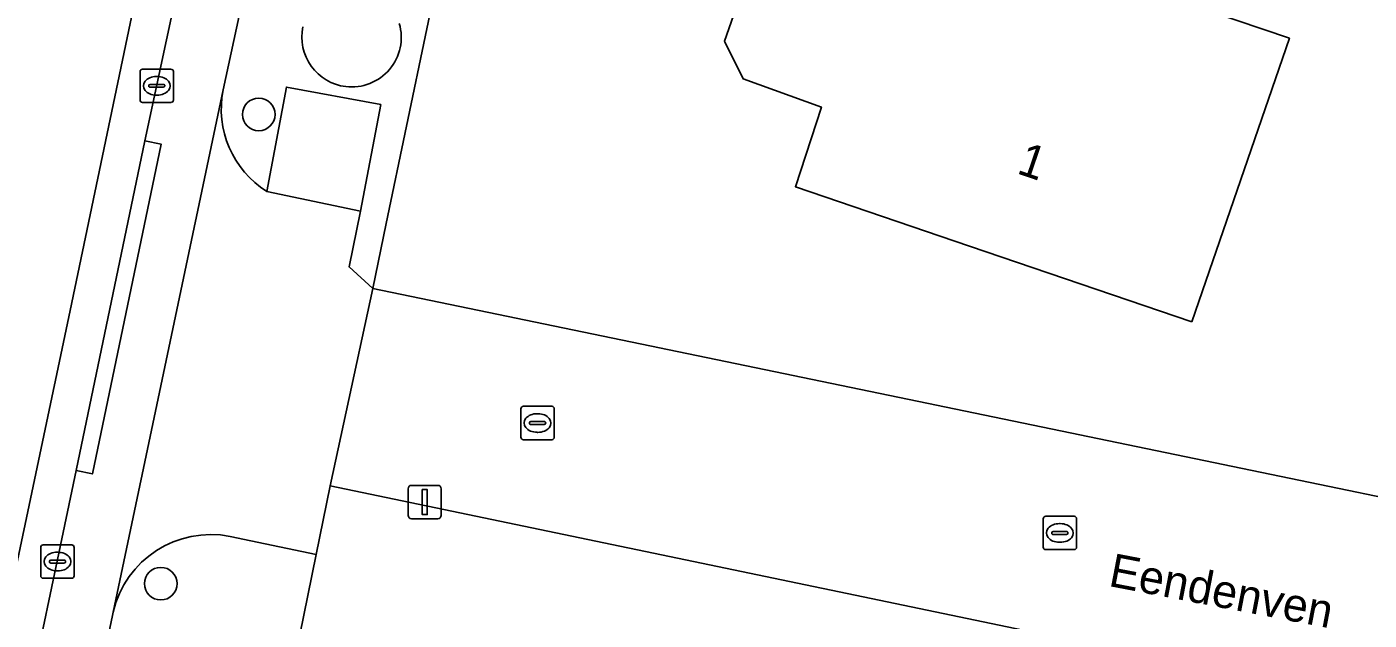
# Model space of a CAD drawing. Extents: x 163426 to 164192, y 380329 to 381641.
# Drawn here: x 163885.21 to 163925.42, y 380973.51 to 380991.3 of the extents above; entities that cross this region are included whole.
import ezdxf

# ---------------------------------------------------------------- set-up
doc = ezdxf.new("R2010")
doc.units = 0
for name, color, linetype in [('IMGEO_Boom', 7, 'Continuous'), ('IMGEO_Erf', 7, 'Continuous'), ('IMGEO_Groenvoorziening', 7, 'Continuous'), ('IMGEO_Kolk', 7, 'Continuous'), ('IMGEO_Lichtmast', 7, 'Continuous'), ('IMGEO_Openbare_ruimte_label', 7, 'Continuous'), ('IMGEO_Pand', 7, 'Continuous'), ('IMGEO_Pand_nummerreeks', 7, 'Continuous'), ('IMGEO_Rijbaan_lokaal_open', 7, 'Continuous'), ('IMGEO_Voetpad_open', 7, 'Continuous'), ('IMGEO_Waterloop', 7, 'Continuous')]:
    doc.layers.add(name, color=color, linetype=linetype)

msp = doc.modelspace()

# ---------------------------------------------------------------- linework, layer by layer
at = {"layer": 'IMGEO_Boom'}
for centre in [(163892.154, 380988.669), (163889.22, 380974.6)]:
    msp.add_circle(centre, 0.489, dxfattribs=at)
at = {"layer": 'IMGEO_Erf'}
for points in [[(163947.717, 380966.396), (163894.299, 380977.535), (163893.879, 380975.478), (163890.647, 380959.592), (163890.731, 380956.366), (163893.555, 380954.822), (163905.172, 380951.086), (163923.758, 380944.858), (164044.028, 380904.553), (164047.573, 380932.485), (164051.149, 380955.68), (164051.075, 380964.76), (164050.906, 381000), (164050.855, 381010.828), (164044.976, 381010.935), (164033.301, 381009.851), (164028.463, 381008.901), (164025.441, 381000), (164017.396, 380976.301), (164021.658, 380974.921), (164011.506, 380944.546), (164004.376, 380947.063), (164007.582, 380956.643)], [(164022.57, 381000), (164024.898, 381006.842), (164025.394, 381008.299), (164023.996, 381008.024), (164000, 381002.141), (163996.432, 381001.266), (163991.135, 381000), (163970.466, 380995.06), (163967.625, 380994.381), (163961.405, 380993.65), (163960.215, 380993.613), (163954.592, 380993.795), (163949.019, 380994.564), (163937.098, 380997.759), (163924.687, 381000), (163899.949, 381004.467), (163899.243, 381001.078), (163899.018, 381000), (163895.976, 380985.403), (163895.569, 380983.45), (163954.825, 380971.177)]]:
    msp.add_lwpolyline(points, dxfattribs=at)
msp.add_lwpolyline([(163920.112, 380982.451), (163913.447, 380984.724), (163908.231, 380986.502), (163909.013, 380988.891), (163906.664, 380989.735), (163906.111, 380990.867), (163906.799, 380992.842), (163907.896, 380993.375), (163910.328, 380992.556), (163911.147, 380994.987), (163923.033, 380990.953)], close=True, dxfattribs=at)
at = {"layer": 'IMGEO_Groenvoorziening'}
for points in [[(163899.018, 381000), (163899.243, 381001.078), (163897.624, 381001.36), (163893.814, 381002.022), (163893.377, 381000), (163891.085, 380989.403)], [(163892.395, 380986.356), (163892.983, 380989.49), (163895.81, 380988.967), (163895.2, 380985.771), (163894.863, 380984.096), (163895.569, 380983.45), (163895.976, 380985.403), (163899.018, 381000)], [(163887.797, 380973.745), (163887.786, 380973.694), (163887.776, 380973.643), (163885.067, 380960.77), (163883.083, 380951.119), (163905.684, 380943.493), (163921.538, 380938.092), (163921.833, 380938.946), (163922.56, 380941.188), (163923.758, 380944.858), (163905.172, 380951.086), (163893.555, 380954.822), (163890.731, 380956.366), (163890.647, 380959.592), (163893.879, 380975.478), (163891.917, 380975.887), (163891.302, 380976.015)]]:
    msp.add_lwpolyline(points, dxfattribs=at)
msp.add_lwpolyline([(163892.395, 380986.356), (163895.2, 380985.771), (163895.81, 380988.967), (163892.983, 380989.49)], close=True, dxfattribs=at)
for centre, radius, start, end in [((163894.937, 380990.984), 1.49, 167.9108, 263.2069), ((163894.936, 380990.982), 1.489, 263.245, 16.1386), ((163893.985, 380988.845), 2.953, 169.1045, 237.4243), ((163890.716, 380973.078), 2.995, 78.7234, 167.1345)]:
    msp.add_arc(centre, radius, start, end, dxfattribs=at)
at = {"layer": 'IMGEO_Kolk'}
for p, q in [((163888.599, 380989.101), (163888.599, 380989.953)), ((163888.674, 380990.027), (163889.526, 380990.027)), ((163889.087, 380989.807), (163889.112, 380989.807)), ((163889.6, 380989.953), (163889.6, 380989.101)), ((163888.858, 380989.521), (163888.858, 380989.533)), ((163889.296, 380989.484), (163888.898, 380989.484)), ((163888.901, 380989.57), (163889.299, 380989.57)), ((163889.342, 380989.533), (163889.342, 380989.521)), ((163889.526, 380989.027), (163888.674, 380989.027)), ((163889.11, 380989.247), (163889.085, 380989.247)), ((163900.008, 380978.991), (163900.008, 380979.843)), ((163900.083, 380979.917), (163900.935, 380979.917)), ((163901.009, 380979.843), (163901.009, 380978.991)), ((163900.267, 380979.411), (163900.267, 380979.423)), ((163900.705, 380979.374), (163900.307, 380979.374)), ((163900.31, 380979.46), (163900.708, 380979.46)), ((163900.496, 380979.697), (163900.521, 380979.697)), ((163900.751, 380979.423), (163900.751, 380979.411)), ((163900.519, 380979.137), (163900.494, 380979.137)), ((163900.935, 380978.917), (163900.083, 380978.917)), ((163915.656, 380975.694), (163915.656, 380976.546)), ((163915.731, 380976.62), (163916.583, 380976.62)), ((163916.657, 380976.546), (163916.657, 380975.694)), ((163915.915, 380976.114), (163915.915, 380976.126)), ((163915.958, 380976.163), (163916.356, 380976.163)), ((163916.144, 380976.4), (163916.169, 380976.4)), ((163916.399, 380976.126), (163916.399, 380976.114)), ((163885.699, 380975.762), (163886.551, 380975.762)), ((163916.353, 380976.077), (163915.955, 380976.077)), ((163916.167, 380975.84), (163916.142, 380975.84)), ((163885.624, 380974.836), (163885.624, 380975.688)), ((163886.112, 380975.542), (163886.137, 380975.542)), ((163886.625, 380975.688), (163886.625, 380974.836)), ((163916.583, 380975.62), (163915.731, 380975.62)), ((163885.883, 380975.256), (163885.883, 380975.268)), ((163886.321, 380975.219), (163885.923, 380975.219)), ((163885.926, 380975.305), (163886.324, 380975.305)), ((163886.135, 380974.982), (163886.11, 380974.982)), ((163886.367, 380975.268), (163886.367, 380975.256)), ((163886.551, 380974.762), (163885.699, 380974.762))]:
    msp.add_line(p, q, dxfattribs=at)
for points in [[(163888.599, 380989.101), (163888.599, 380989.953)], [(163888.674, 380990.027), (163889.526, 380990.027)], [(163889.6, 380989.953), (163889.6, 380989.101)], [(163889.526, 380989.027), (163888.674, 380989.027)], [(163900.008, 380978.991), (163900.008, 380979.843)], [(163900.083, 380979.917), (163900.935, 380979.917)], [(163901.009, 380979.843), (163901.009, 380978.991)], [(163900.935, 380978.917), (163900.083, 380978.917)], [(163915.656, 380975.694), (163915.656, 380976.546)], [(163915.731, 380976.62), (163916.583, 380976.62)], [(163916.657, 380976.546), (163916.657, 380975.694)], [(163885.699, 380975.762), (163886.551, 380975.762)], [(163885.624, 380974.836), (163885.624, 380975.688)], [(163886.625, 380975.688), (163886.625, 380974.836)], [(163916.583, 380975.62), (163915.731, 380975.62)], [(163886.551, 380974.762), (163885.699, 380974.762)]]:
    msp.add_lwpolyline(points, dxfattribs=at)
for centre, radius, start, end in [((163888.676, 380989.951), 0.0765, 91.552, 178.448), ((163888.676, 380989.951), 0.0765, 91.552, 178.448), ((163889.524, 380989.951), 0.0765, 1.552, 88.448), ((163889.524, 380989.951), 0.0765, 1.552, 88.448), ((163888.898, 380989.53), 0.0403, 85.8775, 175.7526), ((163888.895, 380989.52), 0.0366, 178.938, 274.7102), ((163889.299, 380989.527), 0.043, 264.8664, 352.4533), ((163889.303, 380989.532), 0.0386, 1.7309, 96.639), ((163888.676, 380989.103), 0.0765, 181.552, 268.448), ((163888.676, 380989.103), 0.0765, 181.552, 268.448), ((163889.524, 380989.103), 0.0765, 271.552, 358.448), ((163889.524, 380989.103), 0.0765, 271.552, 358.448), ((163900.085, 380979.841), 0.0765, 91.552, 178.448), ((163900.085, 380979.841), 0.0765, 91.552, 178.448), ((163900.933, 380979.841), 0.0765, 1.552, 88.448), ((163900.933, 380979.841), 0.0765, 1.552, 88.448), ((163900.307, 380979.42), 0.0403, 85.8775, 175.7526), ((163900.304, 380979.41), 0.0366, 178.938, 274.7102), ((163900.708, 380979.417), 0.043, 264.8664, 352.4533), ((163900.712, 380979.422), 0.0386, 1.7309, 96.639), ((163900.085, 380978.993), 0.0765, 181.552, 268.448), ((163900.085, 380978.993), 0.0765, 181.552, 268.448), ((163900.933, 380978.993), 0.0765, 271.552, 358.448), ((163900.933, 380978.993), 0.0765, 271.552, 358.448), ((163915.733, 380976.544), 0.0765, 91.552, 178.448), ((163915.733, 380976.544), 0.0765, 91.552, 178.448), ((163916.581, 380976.544), 0.0765, 1.552, 88.448), ((163916.581, 380976.544), 0.0765, 1.552, 88.448), ((163915.955, 380976.123), 0.0403, 85.8775, 175.7526), ((163916.36, 380976.125), 0.0386, 1.7309, 96.639), ((163885.701, 380975.686), 0.0765, 91.552, 178.448), ((163885.701, 380975.686), 0.0765, 91.552, 178.448), ((163886.549, 380975.686), 0.0765, 1.552, 88.448), ((163886.549, 380975.686), 0.0765, 1.552, 88.448), ((163915.952, 380976.113), 0.0366, 178.938, 274.7102), ((163916.356, 380976.12), 0.043, 264.8664, 352.4533), ((163915.733, 380975.696), 0.0765, 181.552, 268.448), ((163915.733, 380975.696), 0.0765, 181.552, 268.448), ((163916.581, 380975.696), 0.0765, 271.552, 358.448), ((163916.581, 380975.696), 0.0765, 271.552, 358.448), ((163885.923, 380975.265), 0.0403, 85.8775, 175.7526), ((163885.92, 380975.255), 0.0366, 178.938, 274.7102), ((163886.324, 380975.262), 0.043, 264.8664, 352.4533), ((163886.328, 380975.267), 0.0386, 1.7309, 96.639), ((163885.701, 380974.838), 0.0765, 181.552, 268.448), ((163885.701, 380974.838), 0.0765, 181.552, 268.448), ((163886.549, 380974.838), 0.0765, 271.552, 358.448), ((163886.549, 380974.838), 0.0765, 271.552, 358.448)]:
    msp.add_arc(centre, radius, start, end, dxfattribs=at)
for centre, major_axis, ratio, start_param, end_param in [((163889.086, 380989.527), (-0.387, 0.002), 0.722429, 4.712389, 7.853982), ((163889.111, 380989.527), (-0.39, 0.002), 0.717154, 1.570796, 4.712389), ((163900.495, 380979.417), (-0.387, 0.002), 0.722429, 4.712389, 7.853982), ((163900.52, 380979.417), (-0.39, 0.002), 0.717154, 1.570796, 4.712389), ((163916.143, 380976.12), (-0.387, 0.002), 0.722429, 4.712389, 7.853982), ((163916.168, 380976.12), (-0.39, 0.002), 0.717154, 1.570796, 4.712389), ((163886.111, 380975.262), (-0.387, 0.002), 0.722429, 4.712389, 7.853982), ((163886.136, 380975.262), (-0.39, 0.002), 0.717154, 1.570796, 4.712389)]:
    msp.add_ellipse(centre, major_axis=major_axis, ratio=ratio, start_param=start_param, end_param=end_param, dxfattribs=at)
at = {"layer": 'IMGEO_Lichtmast'}
for p, q in [((163896.632, 380976.648), (163896.632, 380977.448)), ((163896.632, 380977.448), (163896.632, 380976.648)), ((163896.732, 380977.548), (163897.522, 380977.548)), ((163897.522, 380977.548), (163896.732, 380977.548)), ((163897.622, 380977.448), (163897.622, 380976.648)), ((163897.622, 380976.648), (163897.622, 380977.448)), ((163897.522, 380976.548), (163896.732, 380976.548)), ((163896.732, 380976.548), (163897.522, 380976.548))]:
    msp.add_line(p, q, dxfattribs=at)
msp.add_lwpolyline([(163897.052, 380977.423), (163897.202, 380977.423), (163897.202, 380976.673), (163897.052, 380976.673), (163897.052, 380977.423)], dxfattribs=at)
for centre, start, end in [((163896.732, 380977.448), 90, 180), ((163896.732, 380977.448), 90, 180), ((163897.522, 380977.448), 0, 90), ((163897.522, 380977.448), 360, 90), ((163896.732, 380976.648), 180, 270), ((163896.732, 380976.648), 180, 270), ((163897.522, 380976.648), 270, 0), ((163897.522, 380976.648), 270, 0)]:
    msp.add_arc(centre, 0.1, start, end, dxfattribs=at)
at = {"layer": 'IMGEO_Pand'}
msp.add_lwpolyline([(163920.112, 380982.451), (163923.033, 380990.953), (163911.147, 380994.987), (163910.328, 380992.556), (163907.896, 380993.375), (163906.799, 380992.842), (163906.111, 380990.867), (163906.664, 380989.735), (163909.013, 380988.891), (163908.231, 380986.502), (163913.447, 380984.724)], close=True, dxfattribs=at)
at = {"layer": 'IMGEO_Rijbaan_lokaal_open'}
for points in [[(163921.638, 381053.716), (163922.311, 381054.818), (163921.501, 381055.887), (163917.721, 381049.86), (163902.377, 381023.75), (163895.208, 381011.818), (163892.059, 381006.187), (163890.987, 381003.841), (163890.009, 380999.579), (163886.502, 380982.789), (163875.39, 380930.027), (163874.806, 380927.256), (163873.655, 380925.227), (163872.124, 380924.818), (163868.839, 380925.415), (163868.546, 380923.98), (163875.141, 380922.738), (163879.435, 380943.25), (163880.93, 380950.483), (163883.139, 380961.124), (163886.682, 380977.995), (163888.743, 380987.877), (163891.335, 381000), (163891.536, 381000.938)], [(163909.614, 381043.056), (163891.389, 381012.622), (163887.972, 381006.053), (163887.168, 381003.975), (163886.431, 381000.422), (163877.536, 380958.937), (163873.3, 380937.44), (163872.302, 380935.525), (163871.122, 380934.091), (163870.508, 380933.6), (163868.839, 380925.415), (163872.124, 380924.818), (163873.655, 380925.227), (163874.806, 380927.256), (163875.39, 380930.027), (163886.502, 380982.789), (163890.009, 380999.579), (163890.987, 381003.841), (163892.059, 381006.187), (163895.208, 381011.818), (163902.377, 381023.75)], [(163954.825, 380971.177), (163895.569, 380983.45), (163894.299, 380977.535), (163947.717, 380966.396)]]:
    msp.add_lwpolyline(points, dxfattribs=at)
at = {"layer": 'IMGEO_Voetpad_open'}
for points in [[(163887.776, 380973.643), (163887.786, 380973.694), (163887.797, 380973.745), (163891.085, 380989.403), (163893.377, 381000), (163893.814, 381002.022), (163894.123, 381002.969)], [(163891.536, 381000.938), (163891.335, 381000), (163888.743, 380987.877), (163889.232, 380987.775), (163887.171, 380977.893), (163886.682, 380977.995), (163883.139, 380961.124), (163880.93, 380950.483), (163879.435, 380943.25), (163875.141, 380922.738), (163875.046, 380922.248), (163868.475, 380923.523), (163867.664, 380918.263), (163877.003, 380916.322), (163882.796, 380944.027), (163883.85, 380949.068), (163883.898, 380949.297), (163882.779, 380949.641), (163883.083, 380951.119), (163885.067, 380960.77), (163887.776, 380973.643)], [(163891.085, 380989.403), (163887.797, 380973.745)], [(163895.569, 380983.45), (163894.863, 380984.096), (163895.2, 380985.771), (163892.395, 380986.356)], [(163891.302, 380976.015), (163891.917, 380975.887), (163893.879, 380975.478), (163894.299, 380977.535), (163895.569, 380983.45)]]:
    msp.add_lwpolyline(points, dxfattribs=at)
msp.add_lwpolyline([(163886.682, 380977.995), (163887.171, 380977.893), (163889.232, 380987.775), (163888.743, 380987.877)], close=True, dxfattribs=at)
for centre, radius, start, end in [((163893.985, 380988.845), 2.953, 169.1045, 237.4243), ((163890.716, 380973.078), 2.995, 78.7234, 167.1345)]:
    msp.add_arc(centre, radius, start, end, dxfattribs=at)
at = {"layer": 'IMGEO_Waterloop'}
for centre, radius, start, end in [((163894.937, 380990.984), 1.49, 167.9108, 263.2069), ((163894.936, 380990.982), 1.489, 263.245, 16.1386)]:
    msp.add_arc(centre, radius, start, end, dxfattribs=at)

# ---------------------------------------------------------------- texts
at = {"layer": 'IMGEO_Openbare_ruimte_label'}
msp.add_text('Eendenven', height=1, rotation=349.1621, dxfattribs=at).set_placement((163917.585, 380974.535))
at = {"layer": 'IMGEO_Pand_nummerreeks'}
msp.add_text('1', height=1, rotation=341.1724, dxfattribs=at).set_placement((163914.832, 380986.914))

doc.saveas('drawing.dxf')
